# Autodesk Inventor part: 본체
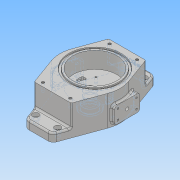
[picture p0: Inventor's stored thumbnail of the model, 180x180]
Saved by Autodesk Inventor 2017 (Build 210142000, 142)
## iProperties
Part Number: 본체
Material: 일반
Document SubType Name: Modeling
Designer: Administrator
Density: 1 g/cm^3
Appearance: 기본값
Author: Administrator
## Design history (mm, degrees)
sketch "스케치1"
  geometry: L1 (-17.315, 94)-(17.315, 94); L2 (-17.315, -94)-(17.315, -94); L3 (-51.683, 18.811)-(-33.78, 68); L4 (26.711, 87.42)-(33.78, 68); L5 (-26.711, -87.42)-(-33.78, -68); L6 (26.711, -87.42)-(33.78, -68); L7 (0.846, 54.993)-(0.846, -54.993); L8 (-33.78, 68)-(33.78, 68); L9 (-33.78, -68)-(33.78, -68); L10 (-33.78, 68)-(-26.711, 87.42); L11 (33.78, 68)-(51.683, 18.811); L12 (33.78, -68)-(51.683, -18.811); L13 (-33.78, -68)-(-51.683, -18.811); A1 r 55 centre (0, 0) between (-51.683, -18.811) and (51.683, -18.811); A2 r 55 centre (0, 0) between (-51.683, 18.811) and (-51.683, -18.811); A3 r 55 centre (0, 0) between (51.683, 18.811) and (-51.683, 18.811); A4 r 55 centre (0, 0) between (51.683, -18.811) and (51.683, 18.811); A5 r 10 centre (-17.315, -84) between (-26.711, -87.42) and (-17.315, -94); A6 r 10 centre (17.315, -84) between (17.315, -94) and (26.711, -87.42); A7 r 10 centre (-17.315, 84) between (-17.315, 94) and (-26.711, 87.42); A8 r 10 centre (17.315, 84) between (26.711, 87.42) and (17.315, 94); 1 further point
  constraints: 34 tangent, 26 end point, 22 point on circle, 8 centre point, 4 horizontal, 3 equal radius, 1 coincident, 1 vertical
  dimensions: "d0" = 110 diameter of A1; "d1" = 188 distance between parallel lines of L2 L1; "d2" = 94 distance from line of L2 point (0, 0); "d3" = 20 deg angle of L7 L3; "d4" = 40 deg angle of L4 L3; "d5" = 20 deg angle of L5 L7; "d6" = 40 deg angle of L6 L5; "d7" = 10 radius of A5; "d11" = 136 distance between parallel lines of L9 L8; "d12" = 68 distance from line of L9 point (0, 0)
extrude "돌출1" new body sketch "스케치1" distance "d8" = 15; taper "d9" = 0 deg
extrude "돌출2" join sketch "스케치1" distance "d13" = 55; taper "d14" = 0 deg
sketch "스케치20"
  geometry: L1 (-9, 5)-(27, 5); L2 (32, 10)-(32, 30); L3 (27, 35)-(-9, 35); L4 (-14, 30)-(-14, 10); L5 (-14, 5)-(32, 35); L6 (32, 5)-(-14, 35); A1 r 5 centre (27, 30) between (32, 30) and (27, 35); A2 r 5 centre (27, 10) between (27, 5) and (32, 10); A3 r 5 centre (-9, 10) between (-14, 10) and (-9, 5); A4 r 5 centre (-9, 30) between (-9, 35) and (-14, 30); 2 further points
  constraints: 12 end point, 8 point on circle, 8 point on line, 8 tangent, 4 centre point, 3 equal radius, 2 midpoint, 2 parallel, 1 horizontal, 1 perpendicular
  dimensions: "d104" = 9 horizontal distance of point (9, 20) point (0, 0); "d105" = 20 vertical distance of point (9, 20) point (0, 0); "d106" = 46 distance of L5.end L6.end; "d107" = 30 distance of L6.start L5.end; "d110" = 5 radius of A1 (derived)
extrude "돌출11" join sketch "스케치20" stored distance "d108" = 118; taper "d109" = 0 deg
sketch "스케치3"
  geometry: C1 r 17.5 at (0, 0); A1 r 55 centre (0, 0) between (51.683, -18.811) and (51.683, 18.811) reference
  constraints: 1 centre point, 1 coincident
  dimensions: "d15" = 35 diameter of C1
extrude "돌출3" join sketch "스케치3" distance "d16" = 5; taper "d17" = 0 deg
sketch "스케치7"
  geometry: C1 r 40 at (0, 9); A1 r 55 centre (0, 0) between (-51.683, 18.811) and (-51.683, -18.811) reference
  constraints: 1 centre point, 1 vertical alignment
  dimensions: "d33" = 80 diameter of C1; "d34" = 9 distance of A1.centre C1.centre
extrude "돌출7" cut sketch "스케치7" distance "d35" = 30; taper "d36" = 0 deg
sketch "스케치8"
  geometry: C1 r 40 at (0, 9) reference; C2 r 47.5 at (0, 9); C3 r 43.4 at (0, 9)
  constraints: 2 centre point, 1 coincident
  dimensions: "d37" = 95 diameter of C2; "d38" = 4.1 radial gap between concentric circles of C2 C3
extrude "돌출8" cut sketch "스케치8" distance "d39" = 2.4; taper "d40" = 0 deg
sketch "스케치12"
  geometry: L1 (-40, 25)-(40, 25) reference; L2 (0, 0)-(0, 25); L3 (10, 25)-(10, 15); L4 (10, 15)-(8, 15); L5 (8, 15)-(8, 3.4); L6 (8, 3.4)-(12.3, 3.4); L7 (12.5, 3.2)-(12.5, -5); L8 (-17.5, -5)-(17.5, -5) reference; L9 (12.5, -5)-(0, -5); L10 (0, 0)-(0, -5); L11 (10, 25)-(0, 25); A1 r 0.2 centre (12.3, 3.2) between (12.5, 3.2) and (12.3, 3.4); 1 further point
  constraints: 18 end point, 5 perpendicular, 4 point on line, 2 midpoint, 2 point on circle, 2 tangent, 1 centre point, 1 horizontal, 1 vertical
  dimensions: "d51" = 20 diameter of L3 L2; "d52" = 10 distance of L3.start L3.end; "d53" = 16 diameter of L5 L2; "d54" = 25 diameter of L7 L10; "d55" = 8.4 distance of point (12.5, 3.4) L7.end; "d56" = 0.2 radius of A1
revolve "회전1" sketch "스케치12" stored, may be unused: angle "d57" = 90 deg
sketch "스케치15"
  geometry: A1 r 55 centre (0, 0) between (-51.683, 18.811) and (-51.683, -18.811) reference; 4 further points
  constraints: 2 horizontal alignment, 2 vertical alignment
  dimensions: "d73" = 50 distance of point (25, -61) point (-25, -61); "d74" = 25 horizontal distance of point (-25, -61) A1.centre; "d76" = 122 distance of point (-25, 61) point (-25, -61); "d77" = 61 vertical distance of A1.centre point (-25, -61)
hole "구멍4" sketch "스케치15" at (-25, -61), (25, -61), (-25, 61), (25, 61) diameter "d78" = 4.917; stored, may be unused: countersink angle "d82" = 90 deg, drill point angle "d84" = 118 deg; dims "d79" = 12, "d80" = 11, "d81" = 6.6, "d83" = 14
sketch "스케치17"
  geometry: L1 (26.702, 6)-(22.517, 6); L2 (-22.517, 6)-(-26.702, 6); L3 (26.702, -6)-(25.515, -6); L4 (-25.515, -6)-(-26.702, -6); C1 r 10 at (0, -9) reference; C2 r 40 at (0, 0) reference; A1 r 24 centre (0, -9) between (-20.785, 3) and (-23.552, -4.385); A2 r 29 centre (0, 0) between (-28.68, 4.296) and (-28.68, -4.296); A3 r 24 centre (0, -9) between (18.735, 6) and (-18.735, 6); A4 r 29 centre (0, 0) between (28.373, 6) and (-28.373, 6); A5 r 29 centre (0, 0) between (-28.373, -6) and (28.373, -6); A6 r 24 centre (0, -9) between (-23.812, -6) and (23.812, -6); A7 r 24 centre (0, -9) between (23.552, -4.385) and (20.785, 3); A8 r 29 centre (0, 0) between (28.68, -4.296) and (28.68, 4.296); A9 r 2 centre (-22.517, 4) between (-20.785, 3) and (-22.517, 6); A10 r 2 centre (-25.515, -4) between (-25.515, -6) and (-23.552, -4.385); A11 r 2 centre (-26.702, -4) between (-28.68, -4.296) and (-26.702, -6); A12 r 2 centre (-26.702, 4) between (-26.702, 6) and (-28.68, 4.296); A13 r 2 centre (22.517, 4) between (22.517, 6) and (20.785, 3); A14 r 2 centre (26.702, 4) between (28.68, 4.296) and (26.702, 6); A15 r 2 centre (25.515, -4) between (23.552, -4.385) and (25.515, -6); A16 r 2 centre (26.702, -4) between (26.702, -6) and (28.68, -4.296)
  constraints: 41 point on circle, 16 centre point, 16 tangent, 8 end point, 8 point on line, 7 equal radius, 4 horizontal, 2 coincident, 1 collinear
  dimensions: "d89" = 12 distance between parallel lines of L3 L1; "d90" = 12 distance between parallel lines of L4 L2; "d91" = 6 distance from line of L4 C2.centre; "d92" = 48 diameter of A1; "d93" = 58 diameter of A2; "d94" = 2 radius of A9 (derived)
extrude "돌출10" cut sketch "스케치17" distance "d95" = 12; taper "d96" = 0 deg
fillet "모깎기1" dims "d97" = 2
sketch "스케치22"
  geometry: L1 (0, 18.811)-(0, -18.811) reference; 2 further points
  dimensions: "d113" = 9 vertical distance of point (0, 0) point (-20, 9); "d114" = 20 distance from line of point (-20, 9) L1
hole "구멍5" sketch "스케치22" at (-20, 9) diameter "d115" = 6; stored, may be unused: countersink angle "d119" = 90 deg, drill point angle "d121" = 118 deg; dims "d116" = 12, "d117" = 11, "d118" = 6.6, "d120" = 14
sketch "스케치23"
  geometry: C1 r 3 at (-20, 9) reference; 5 further points
  constraints: 2 horizontal alignment, 2 vertical alignment
  dimensions: "d122" = 17 vertical distance of point (-29, 26) C1.centre; "d123" = 34 distance of point (-29, 26) point (-29, -8); "d124" = 9 horizontal distance of point (-29, 26) C1.centre; "d125" = 18 distance of point (-11, 26) point (-29, 26)
hole "구멍6" sketch "스케치23" at (-29, 26), (-11, 26), (-11, -8), (-29, -8) diameter "d126" = 3.242; stored, may be unused: countersink angle "d130" = 90 deg, drill point angle "d132" = 118 deg; dims "d127" = 8, "d128" = 11, "d129" = 6.6, "d131" = 10
sketch "스케치24"
  geometry: A1 r 24 centre (0, -9) between (-20.785, 3) and (-23.552, -4.385) reference; 2 further points
  constraints: 1 horizontal alignment
  dimensions: "d133" = 26 vertical distance of point (15, 17) A1.centre; "d134" = 30 distance of point (15, 17) point (-15, 17); "d135" = 15 horizontal distance of A1.centre point (15, 17)
hole "구멍7" sketch "스케치24" at (-15, 17), (15, 17) diameter "d136" = 3.242; stored, may be unused: countersink angle "d140" = 90 deg, drill point angle "d142" = 118 deg; dims "d137" = 8, "d138" = 11, "d139" = 6.6, "d141" = 10
sketch "스케치25"
  geometry: L1 (67.56, -40)-(0, -40) reference; L2 (8.892, -21.398)-(58.667, -21.398); L3 (58.667, -21.398)-(58.667, -28.602); L4 (58.667, -28.602)-(8.892, -28.602); L5 (8.892, -28.602)-(8.892, -21.398); L6 (51.094, 15)-(16.465, 15) reference; L7 (58.667, -25)-(8.892, -25); 3 further points
  constraints: 4 midpoint, 2 end point, 1 vertical alignment, 2 other
  dimensions: "d143" = 15 distance between parallel lines of L1 L7
feature "엠보싱1" sketch "스케치25" dims "d0" = 110, "d1" = 188, "d2" = 94, "d3" = 20 deg, "d4" = 40 deg, "d5" = 20 deg, "d6" = 40 deg, "d7" = 10, "d11" = 136, "d12" = 68, "d144" = 0.5, "d145" = 0
chamfer "모따기1" distance "d146" = 1; stored, may be unused: second distance "d147" = 2, angle "d148" = 30 deg
fillet "모깎기4" dims "d154" = 3
fillet "모깎기5" dims "d155" = 3
chamfer "모따기3" distance "d156" = 0.4; stored, may be unused: second distance "d157" = 2, angle "d158" = 30 deg
fillet "모깎기6" dims "d159" = 0.5
sketch "스케치26"
  geometry: 5 further points
  constraints: 2 horizontal alignment
  dimensions: "d160" = 79 vertical distance of point (20, -79) point (0, 0); "d161" = 40 distance of point (20, -79) point (-20, -79); "d162" = 20 horizontal distance of point (0, 0) point (20, -79); "d163" = 40 distance of point (20, 79) point (-20, 79); "d164" = 20 horizontal distance of point (0, 0) point (20, 79); "d165" = 158 distance of point (20, 79) point (20, -79)
hole "구멍8" sketch "스케치26" at (-20, -79), (20, -79), (-20, 79), (20, 79) diameter "d166" = 6.6; stored, may be unused: countersink angle "d170" = 90 deg, drill point angle "d172" = 118 deg; dims "d167" = 8, "d168" = 11, "d169" = 6.6, "d171" = 10
node "솔리드1"
mirror "미러1"
other parameters: "d85" = 48, "d86" = 58, "d87" = 6, "d88" = 12
